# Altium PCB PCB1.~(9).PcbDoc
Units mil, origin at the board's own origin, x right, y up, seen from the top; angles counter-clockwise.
Board outline 1890 x 1900 mil, 2 copper layers (Top Layer, Bottom Layer); 27 components, 29 nets, 115 pads, 22 vias.
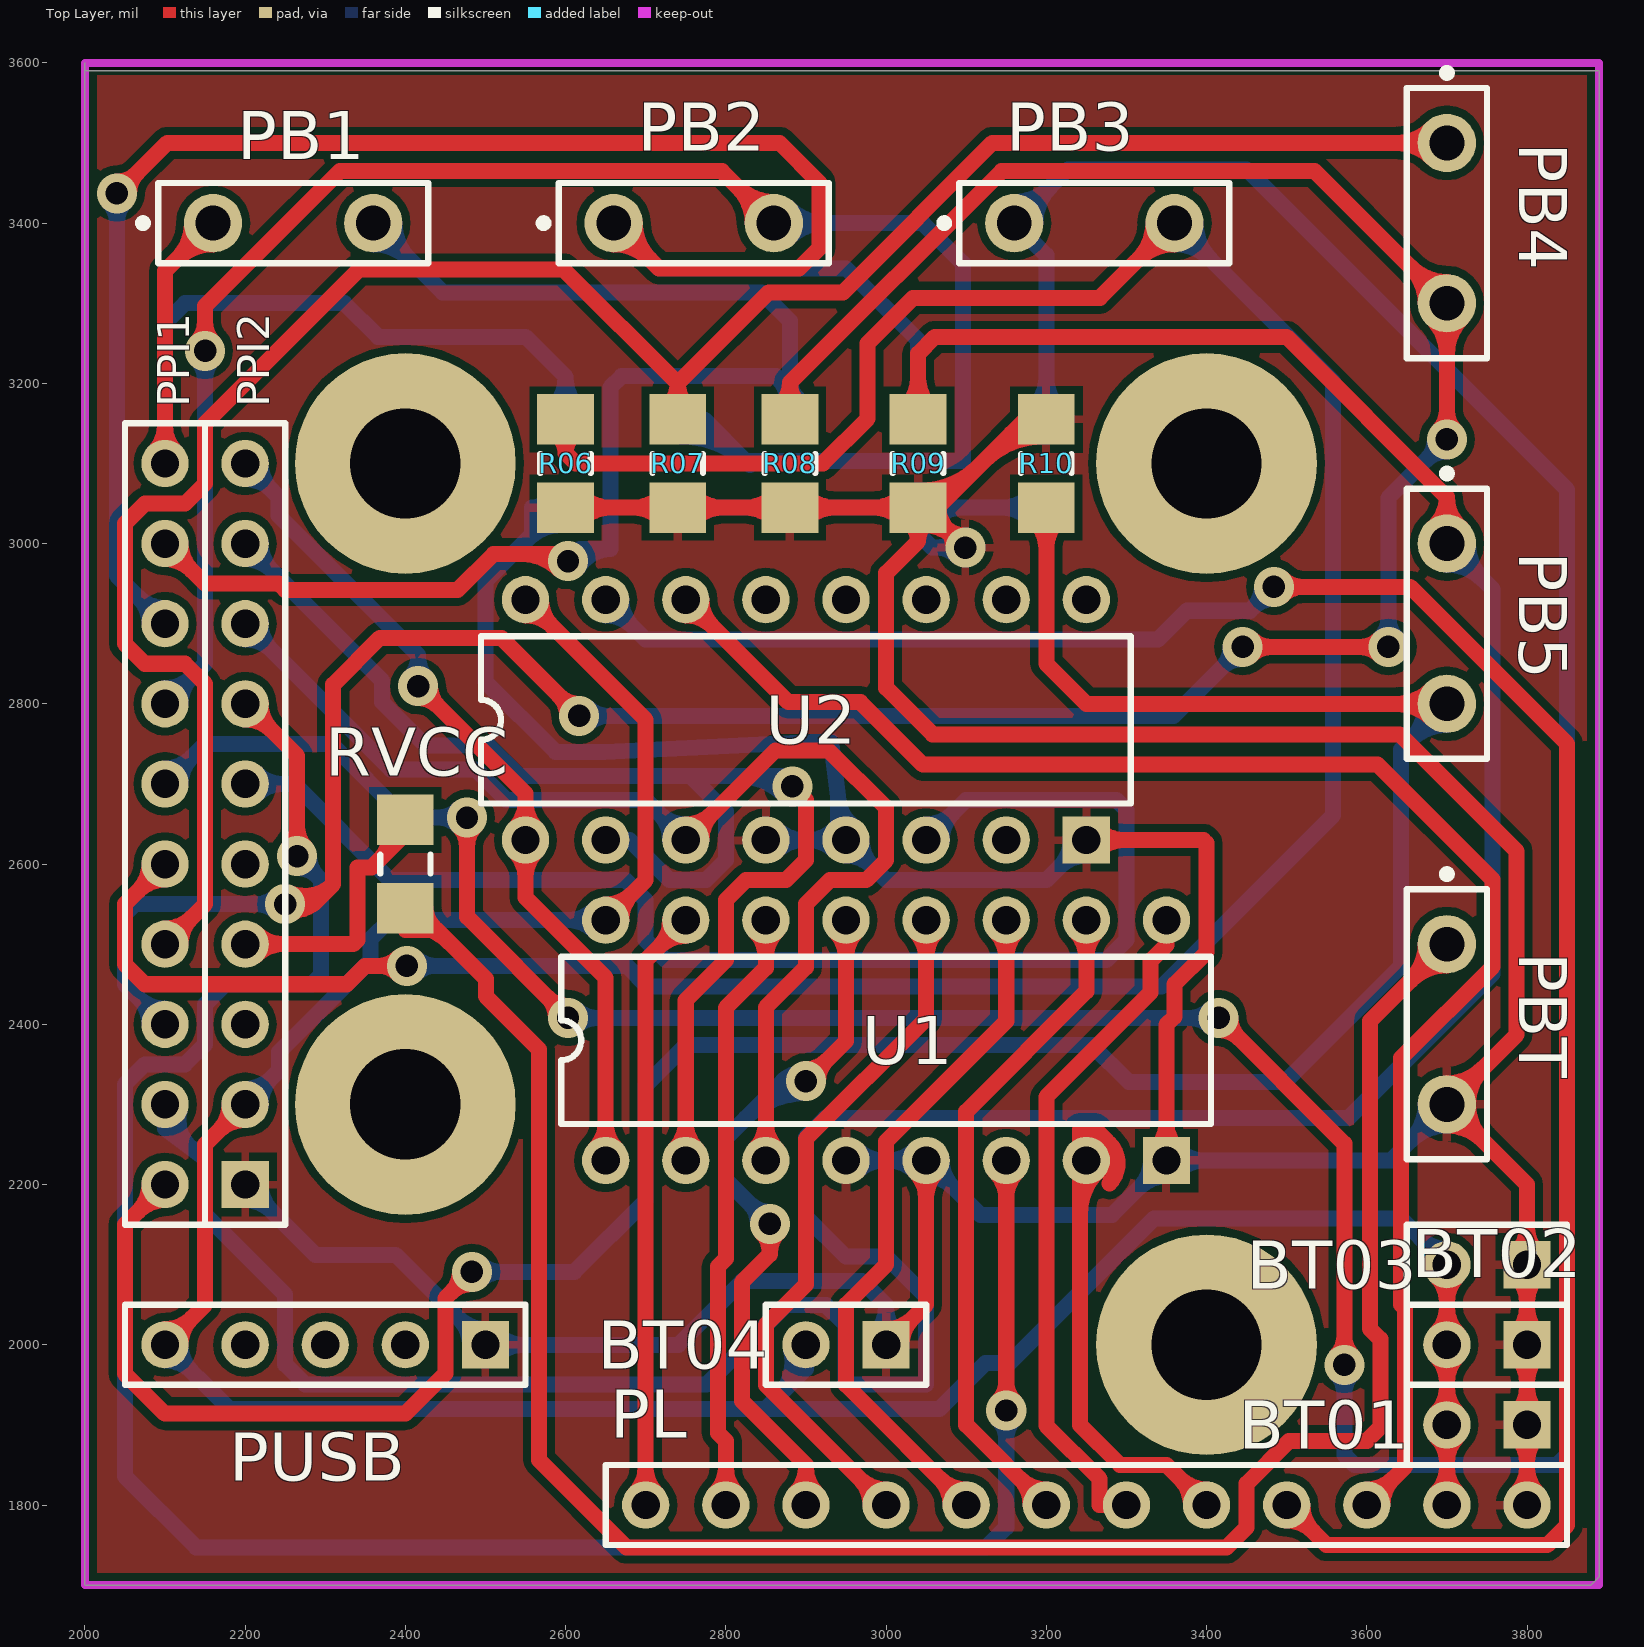
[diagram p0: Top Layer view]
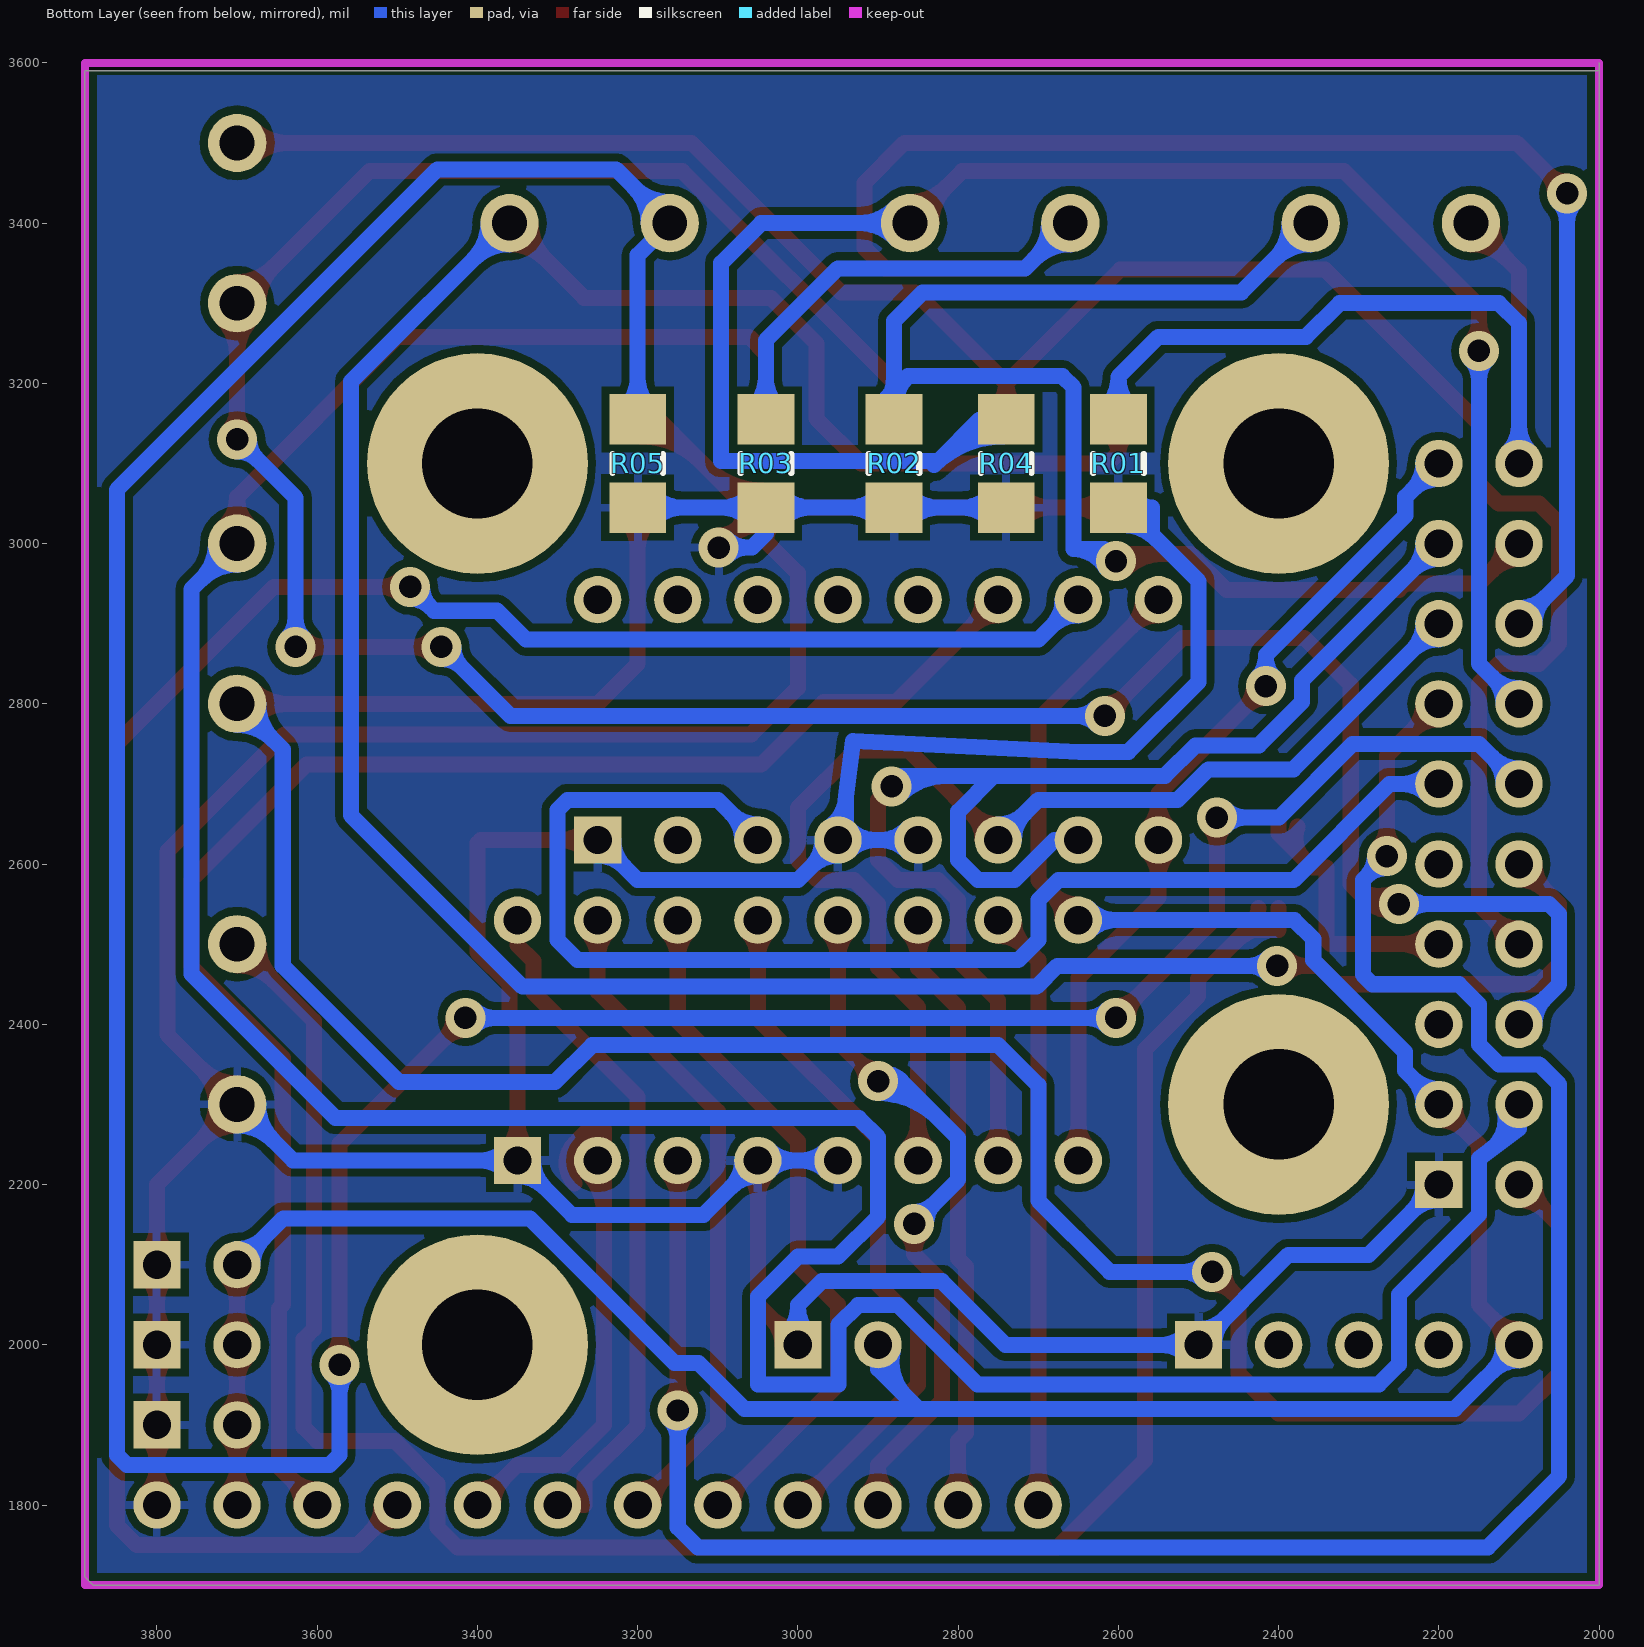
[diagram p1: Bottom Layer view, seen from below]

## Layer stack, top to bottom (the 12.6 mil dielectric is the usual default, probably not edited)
Top Layer: signal copper 1.4
Dielectric: dielectric 12.6, FR-4, Dk 4.8
Bottom Layer: signal copper 1.4

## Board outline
2010,3590 3890,3590 3890,1710 3880,1700 2000,1700 2000,3600 2000,3590

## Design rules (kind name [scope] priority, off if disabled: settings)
Clearance [All] p1: gap=10
ComponentClearance [All] p1: gap=10 collisioncheckmode=3 verticalgap=10
PolygonConnect [All] p1: connectstyle=Relief reliefconductorwidth=10 reliefentries=4 polygonreliefangle="90 Angle"
RoutingVias [All] p1: holewidth=28 width=50 viastyle="Through Hole" minholewidth=28 minwidth=50 maxholewidth=28 maxwidth=50
SolderMaskExpansion [All] p1: expansion=4
TestPointUsage [All] p1: valid=0 allowmultiple=FALSE
Testpoint [All] p1: side=15 testpointundercomponent=TRUE minsize=40 maxsize=100 preferedsize=60 minholesize=0 maxholesize=40 preferedholesize=32 testpointgrid=1 style=1023 order=0123456789
Width Width_2 [All] p1: maxlimit=30 minlimit=15 preferedwidth=20
Width Width_1 [InNet('VCC')] p2: maxlimit=30 minlimit=20 preferedwidth=30
Width [InNet('GND')] p3: maxlimit=30 minlimit=20 preferedwidth=30
18 further rules are at their usual default settings.

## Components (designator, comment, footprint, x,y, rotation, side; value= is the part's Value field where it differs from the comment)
BT01 "Header 2" HDR1X2 3800,1900 r180 top
BT02 "Header 2" HDR1X2 3800,2000 r180 top
BT03 "Header 2" HDR1X2 3800,2100 r180 top
BT04 "Header 2" HDR1X2 3000,2000 r180 top
PB1 "Header 2" SPST-2 2260,3400 r0 top
PB2 "Header 2" SPST-2 2760,3400 r0 top
PB3 "Header 2" SPST-2 3260,3400 r0 top
PB4 "Header 2" SPST-2 3700,3400 r270 top
PB5 "Header 2" SPST-2 3700,2900 r270 top
PBT "Header 2" SPST-2 3700,2400 r270 top
PL "Header 12" HDR1X12 2700,1800 r0 top
PPI1 "Header 10" HDR1X10#1 2100,3100 r270 top
PPI2 "Header 10" HDR1X10#2 2200,3100 r270 top
PUSB "Header 5" HDR1X5 2100,2000 r0 top
R01 "Res1" 3216[1206] 2600,3100 r90 bottom
R02 "Res1" 3216[1206] 2880,3100 r90 bottom
R03 "Res1" 3216[1206] 3040,3100 r90 bottom
R04 "Res1" 3216[1206] 2740,3100 r90 bottom
R05 "Res1" 3216[1206] 3200,3100 r90 bottom
R06 "Res1" 3216[1206] 2600,3100 r90 top
R07 "Res1" 3216[1206] 2740,3100 r90 top
R08 "Res1" 3216[1206] 2880,3100 r90 top
R09 "Res1" 3216[1206] 3040,3100 r90 top
R10 "Res1" 3216[1206] 3200,3100 r270 top
RVCC "Res1" 3216[1206] 2400,2600 r90 top
U1 "SN74HC138D" DIP-16 3000,2380 r0 top
U2 "SN74HC138D" DIP-16 2900,2780 r0 top

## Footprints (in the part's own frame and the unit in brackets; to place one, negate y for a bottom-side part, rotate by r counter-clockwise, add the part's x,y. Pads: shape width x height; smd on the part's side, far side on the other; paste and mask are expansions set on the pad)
3216[1206] [mm] "Chip Resistor; Body 3.2 x 1.6 mm (LxW typ)"
  rect 1.6x1.8 smd: 1(-1.4,0) 2(1.4,0)
  silkscreen extent -0.3,-0.8 0.3,0.8
DIP-16 [mm] "DIP; 16 Leads; Row Spacing 7.62 mm; Pitch 2.54 mm"
  round 1.5 hole 0.9: 1(-8.89,-3.81) 2(-6.35,-3.81) 3(-3.81,-3.81) 4(-1.27,-3.81) 5(1.27,-3.81) 6(3.81,-3.81) 7(6.35,-3.81) 9(8.89,3.81) 10(6.35,3.81) 11(3.81,3.81) 12(1.27,3.81) 13(-1.27,3.81) 14(-3.81,3.81) 15(-6.35,3.81) 16(-8.89,3.81)
  rect 1.5x1.5 hole 0.9: 8(8.89,-3.81)
  silkscreen extent -10.3,-2.65 10.3,2.65
HDR1X2 [mm] "Connector; Header; 2 Position"
  rect 1.5x1.5 hole 0.9: 1(0,0)
  round 1.5 hole 0.9: 2(2.54,0)
  silkscreen extent -1.27,-1.27 3.81,1.27
HDR1X5 [mm] "Connector; Header; 5 Position"
  round 1.5 hole 0.9: 1(0,0) 2(2.54,0) 3(5.08,0) 4(7.62,0)
  rect 1.5x1.5 hole 0.9: 5(10.16,0)
  silkscreen extent -1.27,-1.27 11.43,1.27
HDR1X10#1 [mm] "Connector; Header; 10 Position"
  round 1.5 hole 0.9: 1(0,0) 2(2.54,0) 3(5.08,0) 4(7.62,0) 5(10.16,0) 6(12.7,0) 7(15.24,0) 8(17.78,0) 9(20.32,0) 10(22.86,0)
  silkscreen extent -1.27,-1.27 24.13,1.27
HDR1X10#2 [mm] "Connector; Header; 10 Position"
  round 1.5 hole 0.9: 1(0,0) 2(2.54,0) 3(5.08,0) 4(7.62,0) 5(10.16,0) 6(12.7,0) 7(15.24,0) 8(17.78,0) 9(20.32,0)
  rect 1.5x1.5 hole 0.9: 10(22.86,0)
  silkscreen extent -1.27,-1.27 24.13,1.27
HDR1X12 [mm] "Connector; Header; 12 Position"
  round 1.5 hole 0.9: 1(0,0) 2(2.54,0) 3(5.08,0) 4(7.62,0) 5(10.16,0) 6(12.7,0) 7(15.24,0) 8(17.78,0) 9(20.32,0) 10(22.86,0) 11(25.4,0) 12(27.94,0)
  silkscreen extent -1.27,-1.27 29.21,1.27
SPST-2 [mm] "Circuit Breaker; 2 Leads"
  round 1.85 hole 1.1: 1(-2.54,0) 2(2.54,0)
  silkscreen extent -4.89,-1.27 4.28,1.27

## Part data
BT01 BT02 BT03 BT04 PB1 PB2 PB3 PB4 PB5 PBT: "Header, 2-Pin"
PL: "Header, 12-Pin"
PPI1 PPI2: "Header, 10-Pin"
PUSB: "Header, 5-Pin"
R01 R02 R03 R04 R05 R06 R07 R08 R09 R10 RVCC: "Resistor"
U1 U2: "3-Line to 8-Line Decoder / Demultiplexer"

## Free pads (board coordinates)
  round 275.59 hole 137.8: 0(3400,3100) 1(2400,3100) 3(3400,2000)
  round 275.59 hole 137.8 paste+0: 2(2400,2300)

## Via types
v1: diameter 50, hole 28, Top Layer to Bottom Layer, 22 vias

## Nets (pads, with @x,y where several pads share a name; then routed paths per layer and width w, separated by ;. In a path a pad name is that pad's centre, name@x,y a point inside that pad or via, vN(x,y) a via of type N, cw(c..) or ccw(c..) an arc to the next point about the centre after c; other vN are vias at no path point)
GND: BT01.1 BT02.1 BT03.1 BT04.1 PBT.2 PL.12 PPI2.10 PUSB.5 R01.1 R02.1 R03.1 R04.1 R05.1 R06.1 R07.1 R08.1 R09.1 R10.1 U1.4 U1.5 U1.8 U2.4 U2.5 U2.8 | length 14839.4
  Top Layer w20: R06.1 R07.1 R08.1 R09.1 ; BT04.1 3050,2050 U1.5 ; v1(3099,2995) R09.1@3049.12,3044.88 ; R10.1 3174.24,3155.12 3064,3044.88 R09.1@3049.12,3044.88 ; U2.8 3396,2630 3400,2626 3400,2490 3360,2450 3360,2409.43 3350,2399.43 U1.8 ; PL.12 BT01.1 BT02.1 BT03.1 3800,2200 PBT.2 3787,2387 3787,2616 3641,2762 3058,2762 3000,2820 3000,2963 3040,3003 ; 2655.83,3044.88 cw(c2655.83,3096.78) 2619.14,3060.08 ccw(c2655.83,3096.78) 2655.83,3044.88 ; 2655.83,3044.88 ccw(c2655.83,2992.99) 2619.14,3029.68 cw(c2655.83,2992.99) 2655.83,3044.88 ; 2684.17,3044.88 cw(c2684.17,2992.99) 2720.86,3029.68 ccw(c2684.17,2992.99) 2684.17,3044.88 ; 2684.17,3044.88 ccw(c2684.17,3096.78) 2720.86,3060.08 cw(c2684.17,3096.78) 2684.17,3044.88 ; 2795.83,3044.88 cw(c2795.83,3096.78) 2759.14,3060.08 ccw(c2795.83,3096.78) 2795.83,3044.88 ; 2795.83,3044.88 ccw(c2795.83,2992.99) 2759.14,3029.68 cw(c2795.83,2992.99) 2795.83,3044.88 ; 2824.17,3044.88 cw(c2824.17,2992.99) 2860.86,3029.68 ccw(c2824.17,2992.99) 2824.17,3044.88 ; 2824.17,3044.88 ccw(c2824.17,3096.78) 2860.86,3060.08 cw(c2824.17,3096.78) 2824.17,3044.88 ; 2935.83,3044.88 cw(c2935.83,3096.78) 2899.14,3060.08 ccw(c2935.83,3096.78) 2935.83,3044.88 ; 2935.83,3044.88 ccw(c2935.83,2992.99) 2899.14,3029.68 cw(c2935.83,2992.99) 2935.83,3044.88 ; 2984.17,3044.88 cw(c2984.17,2992.99) 3020.86,3029.68 ccw(c2984.17,2992.99) 2984.17,3044.88 ; 2984.17,3044.88 ccw(c2984.17,3096.78) 3020.86,3060.08 cw(c2984.17,3096.78) 2984.17,3044.88 ; 3033.34,2033.34 cw(c3000,2066.67) 3000,2019.53 ccw(c3000,2066.67) 3033.34,2033.34 ; 3033.34,2033.34 ccw(c3066.67,2000) 3019.53,2000 cw(c3066.67,2000) 3033.34,2033.34 ; 3040,3003 cw(c3070.05,3003) 3052.53,3027.42 ccw(c3070.05,3003) 3040,3003 ; 3040,3003 ccw(c3009.95,3003) 3027.47,3027.42 cw(c3009.95,3003) 3040,3003 ; 3040,3003 R09.1 ; R09.1 R09.1@3049.12,3044.88 ; 3050,2182.86 cw(c3097.14,2182.86) 3063.81,2216.19 ccw(c3097.14,2182.86) 3050,2182.86 ; 3050,2182.86 ccw(c3002.86,2182.86) 3036.19,2216.19 cw(c3002.86,2182.86) 3050,2182.86 ; R09.1@3073.39,3020.61 cw(c3047.79,2995) 3084,2995 ccw(c3047.79,2995) R09.1@3073.39,3020.61 ; R09.1@3073.39,3020.61 ccw(c3099,3046.21) 3099,3010 cw(c3099,3046.21) R09.1@3073.39,3020.61 ; 3297.14,2630 cw(c3297.14,2677.14) 3263.81,2643.81 ccw(c3297.14,2677.14) 3297.14,2630 ; 3297.14,2630 ccw(c3297.14,2582.86) 3263.81,2616.19 cw(c3297.14,2582.86) 3297.14,2630 ; 3350,2277.14 cw(c3302.86,2277.14) 3336.19,2243.81 ccw(c3302.86,2277.14) 3350,2277.14 ; 3350,2277.14 ccw(c3397.14,2277.14) 3363.81,2243.81 cw(c3397.14,2277.14) 3350,2277.14 ; PBT.2@3726.42,2300 cw(c3790.19,2300) 3745.1,2345.1 ; PBT.2@3726.42,2300 ccw(c3790.19,2300) 3745.1,2254.9 ; PBT.2@3726.42,2300 cw(c3790.19,2300) 3745.1,2345.1 ; PBT.2@3726.42,2300 ccw(c3790.19,2300) 3745.1,2254.9 ; 3745.1,2254.9 ccw(c3700,2209.81) 3700,2273.58 cw(c3700,2209.81) 3745.1,2254.9 ; 3745.1,2345.1 cw(c3700,2390.19) 3700,2326.42 ccw(c3700,2390.19) 3745.1,2345.1 ; 3800,1847.14 cw(c3752.86,1847.14) 3786.19,1813.81 ccw(c3752.86,1847.14) 3800,1847.14 ; 3800,1847.14 ccw(c3847.14,1847.14) 3813.81,1813.81 cw(c3847.14,1847.14) 3800,1847.14 ; 3800,1852.86 cw(c3847.14,1852.86) 3813.81,1886.19 ccw(c3847.14,1852.86) 3800,1852.86 ; 3800,1852.86 ccw(c3752.86,1852.86) 3786.19,1886.19 cw(c3752.86,1852.86) 3800,1852.86 ; 3800,1947.14 cw(c3752.86,1947.14) 3786.19,1913.81 ccw(c3752.86,1947.14) 3800,1947.14 ; 3800,1947.14 ccw(c3847.14,1947.14) 3813.81,1913.81 cw(c3847.14,1947.14) 3800,1947.14 ; 3800,1952.86 cw(c3847.14,1952.86) 3813.81,1986.19 ccw(c3847.14,1952.86) 3800,1952.86 ; 3800,1952.86 ccw(c3752.86,1952.86) 3786.19,1986.19 cw(c3752.86,1952.86) 3800,1952.86 ; 3800,2047.14 cw(c3752.86,2047.14) 3786.19,2013.81 ccw(c3752.86,2047.14) 3800,2047.14 ; 3800,2047.14 ccw(c3847.14,2047.14) 3813.81,2013.81 cw(c3847.14,2047.14) 3800,2047.14 ; 3800,2052.86 cw(c3847.14,2052.86) 3813.81,2086.19 ccw(c3847.14,2052.86) 3800,2052.86 ; 3800,2052.86 ccw(c3752.86,2052.86) 3786.19,2086.19 cw(c3752.86,2052.86) 3800,2052.86 ; 3800,2147.14 cw(c3752.86,2147.14) 3786.19,2113.81 ccw(c3752.86,2147.14) 3800,2147.14 ; 3800,2147.14 ccw(c3847.14,2147.14) 3813.81,2113.81 cw(c3847.14,2147.14) 3800,2147.14 ; R09.1@3043.94,3023.39 cw(c3043.94,2958.98) 3089.48,3004.52 ccw(c3043.94,2958.98) R09.1@3043.94,3023.39 ; R09.1@3043.94,3046.38 ccw(c3043.94,3098.43) 3080.74,3061.62 cw(c3043.94,3098.43) R09.1@3043.94,3046.38 ; R09.1@3043.94,3066.38 ccw(c3043.94,3166.71) 3114.88,3095.76 cw(c3043.94,3166.71) R09.1@3043.94,3066.38 ; R09.1@3065.43,3044.88 ccw(c3104.82,3044.88) 3076.97,3017.03 cw(c3104.82,3044.88) R09.1@3065.43,3044.88 ; 3122.11,3102.99 cw(c3196.06,3029.03) 3196.06,3133.62 ccw(c3196.06,3029.03) 3122.11,3102.99 ; 3156.25,3137.13 cw(c3196.06,3097.32) 3196.06,3153.62 ccw(c3196.06,3097.32) 3156.25,3137.13
  Bottom Layer w20: PPI2.10 2287.8,2112.2 2387.8,2112.2 PUSB.5 2740.94,2000 2820.47,2079.53 2970,2079.53 3000,2049.53 BT04.1 ; R01.1 2558,3044.88 ; R04.1 R02.1 R03.1 ; U2.4 U2.5@2940,2630 ; U1.4 U1.5 3118.02,2161.98 3281.98,2161.98 U1.8 3630,2230 PBT.2 ; v1(3099,2995) 3057.5,2995 3040,3012.5 R03.1 ; R05.1 R03.1 ; U2.8 3200,2580 3000,2580 U2.5 U2.5@2940,2630 ; 2233.34,2166.66 cw(c2266.67,2200) 2219.53,2200 ccw(c2266.67,2200) 2233.34,2166.66 ; 2233.34,2166.66 ccw(c2200,2133.33) 2200,2180.47 cw(c2200,2133.33) 2233.34,2166.66 ; 2466.66,2033.34 cw(c2433.33,2000) 2480.47,2000 ccw(c2433.33,2000) 2466.66,2033.34 ; 2466.66,2033.34 ccw(c2500,2066.67) 2500,2019.53 cw(c2500,2066.67) 2466.66,2033.34 ; 2547.14,2000 cw(c2547.14,2047.14) 2513.81,2013.81 ccw(c2547.14,2047.14) 2547.14,2000 ; 2547.14,2000 ccw(c2547.14,1952.86) 2513.81,1986.19 cw(c2547.14,1952.86) 2547.14,2000 ; 2558,3044.88 cw(c2558,3021.93) 2577.65,3033.78 ccw(c2558,3021.93) 2558,3044.88 ; 2558,3044.88 ccw(c2558,3067.83) 2577.65,3055.98 cw(c2558,3067.83) 2558,3044.88 ; 2558,3044.88 2558,3010.86 2500,2952.86 2500,2827.5 2587.5,2740 2648.45,2740 2931.45,2753.55 2940,2684.96 ; 2562.23,3015.09 ccw(c2532.43,3044.88) R01.1@2574.57,3044.88 ; 2562.23,3015.09 ccw(c2532.43,3044.88) R01.1@2574.57,3044.88 ; 2562.23,3015.09 ccw(c2532.43,3044.88) R01.1@2574.57,3044.88 ; 2562.23,3015.09 ccw(c2532.43,3044.88) R01.1@2574.57,3044.88 ; 2795.83,3044.88 cw(c2795.83,3096.78) 2759.14,3060.08 ccw(c2795.83,3096.78) 2795.83,3044.88 ; 2795.83,3044.88 ccw(c2795.83,2992.99) 2759.14,3029.68 cw(c2795.83,2992.99) 2795.83,3044.88 ; 2824.17,3044.88 cw(c2824.17,2992.99) 2860.86,3029.68 ccw(c2824.17,2992.99) 2824.17,3044.88 ; 2824.17,3044.88 ccw(c2824.17,3096.78) 2860.86,3060.08 cw(c2824.17,3096.78) 2824.17,3044.88 ; 2897.14,2630 cw(c2897.14,2677.14) 2863.81,2643.81 ccw(c2897.14,2677.14) 2897.14,2630 ; 2897.14,2630 ccw(c2897.14,2582.86) 2863.81,2616.19 cw(c2897.14,2582.86) 2897.14,2630 ; 2902.86,2630 cw(c2902.86,2582.86) 2936.19,2616.19 ccw(c2902.86,2582.86) 2902.86,2630 ; 2902.86,2630 ccw(c2902.86,2677.14) 2936.19,2643.81 cw(c2902.86,2677.14) 2902.86,2630 ; 2935.83,3044.88 cw(c2935.83,3096.78) 2899.14,3060.08 ccw(c2935.83,3096.78) 2935.83,3044.88 ; 2935.83,3044.88 ccw(c2935.83,2992.99) 2899.14,3029.68 cw(c2935.83,2992.99) 2935.83,3044.88 ; U2.5@2940,2630 2940,2684.96 ; 2940,2684.95 ccw(c2986.37,2684.95) 2960.78,2646.28 cw(c2986.37,2684.95) 2940,2684.95 ; 2983.34,2596.66 cw(c3016.67,2630) 2969.53,2630 ccw(c3016.67,2630) 2983.34,2596.66 ; 2983.34,2596.66 ccw(c2950,2563.33) 2950,2610.47 cw(c2950,2563.33) 2983.34,2596.66 ; 2984.17,3044.88 cw(c2984.17,2992.99) 3020.86,3029.68 ccw(c2984.17,2992.99) 2984.17,3044.88 ; 2984.17,3044.88 ccw(c2984.17,3096.78) 3020.86,3060.08 cw(c2984.17,3096.78) 2984.17,3044.88 ; 2997.14,2230 cw(c2997.14,2277.14) 2963.81,2243.81 ccw(c2997.14,2277.14) 2997.14,2230 ; 2997.14,2230 ccw(c2997.14,2182.86) 2963.81,2216.19 cw(c2997.14,2182.86) 2997.14,2230 ; 3000,2047.14 cw(c2952.86,2047.14) 2986.19,2013.81 ccw(c2952.86,2047.14) 3000,2047.14 ; 3000,2047.14 ccw(c3047.14,2047.14) 3013.81,2013.81 cw(c3047.14,2047.14) 3000,2047.14 ; 3002.86,2230 cw(c3002.86,2182.86) 3036.19,2216.19 ccw(c3002.86,2182.86) 3002.86,2230 ; 3002.86,2230 ccw(c3002.86,2277.14) 3036.19,2243.81 cw(c3002.86,2277.14) 3002.86,2230 ; 3062.79,2995 cw(c3062.79,2958.79) 3088.39,2984.39 ccw(c3062.79,2958.79) 3062.79,2995 ; 3062.79,2995 ccw(c3062.79,3031.21) 3088.39,3005.61 cw(c3062.79,3031.21) 3062.79,2995 ; 3083.34,2196.66 cw(c3116.67,2230) 3069.53,2230 ccw(c3116.67,2230) 3083.34,2196.66 ; 3083.34,2196.66 ccw(c3050,2163.33) 3050,2210.47 cw(c3050,2163.33) 3083.34,2196.66 ; 3095.83,3044.88 cw(c3095.83,3096.78) 3059.14,3060.08 ccw(c3095.83,3096.78) 3095.83,3044.88 ; 3095.83,3044.88 ccw(c3095.83,2992.99) 3059.14,3029.68 cw(c3095.83,2992.99) 3095.83,3044.88 ; 3144.17,3044.88 cw(c3144.17,2992.99) 3180.86,3029.68 ccw(c3144.17,2992.99) 3144.17,3044.88 ; 3144.17,3044.88 ccw(c3144.17,3096.78) 3180.86,3060.08 cw(c3144.17,3096.78) 3144.17,3044.88 ; 3216.66,2596.66 cw(c3250,2563.33) 3250,2610.47 ccw(c3250,2563.33) 3216.66,2596.66 ; 3216.66,2596.66 ccw(c3183.33,2630) 3230.47,2630 cw(c3183.33,2630) 3216.66,2596.66 ; 3316.66,2196.66 cw(c3350,2163.33) 3350,2210.47 ccw(c3350,2163.33) 3316.66,2196.66 ; 3316.66,2196.66 ccw(c3283.33,2230) 3330.47,2230 cw(c3283.33,2230) 3316.66,2196.66 ; 3397.14,2230 cw(c3397.14,2277.14) 3363.81,2243.81 ccw(c3397.14,2277.14) 3397.14,2230 ; 3397.14,2230 ccw(c3397.14,2182.86) 3363.81,2216.19 cw(c3397.14,2182.86) 3397.14,2230 ; 3654.9,2254.9 cw(c3700,2209.81) 3700,2273.58 ccw(c3700,2209.81) 3654.9,2254.9 ; 3654.9,2254.9 ccw(c3609.81,2300) 3673.58,2300 cw(c3609.81,2300) 3654.9,2254.9 ; 2552.47,3005.33 cw(c2596.06,2961.73) 2596.06,3023.39 ccw(c2596.06,2961.73) 2552.47,3005.33 ; 2555.98,3008.84 cw(c2591.45,2973.37) 2594.68,3023.43 ccw(c2591.45,2973.37) 2555.98,3008.84
NetPB1_1: PB1.1 PPI1.1 R01.2 | length 1760.8
  Top Layer w20: PPI1.1 2100,3340 PB1.1 ; 2100,3147.14 cw(c2052.86,3147.14) 2086.19,3113.81 ccw(c2052.86,3147.14) 2100,3147.14 ; 2100,3147.14 ccw(c2147.14,3147.14) 2113.81,3113.81 cw(c2147.14,3147.14) 2100,3147.14 ; 2114.9,3354.9 cw(c2160,3309.81) 2160,3373.58 ccw(c2160,3309.81) 2114.9,3354.9 ; 2114.9,3354.9 ccw(c2069.81,3400) 2133.58,3400 cw(c2069.81,3400) 2114.9,3354.9
  Bottom Layer w20: PPI1.1 2100,3275 2125,3300 2324,3300 2366,3258 2550,3258 2600,3208 R01.2 ; 2100,3147.14 cw(c2052.86,3147.14) 2086.19,3113.81 ccw(c2052.86,3147.14) 2100,3147.14 ; 2100,3147.14 ccw(c2147.14,3147.14) 2113.81,3113.81 cw(c2147.14,3147.14) 2100,3147.14 ; 2600,3207.01 cw(c2548.1,3207.01) 2584.8,3170.32 ccw(c2548.1,3207.01) 2600,3207.01 ; 2600,3207.01 ccw(c2651.9,3207.01) 2615.2,3170.32 cw(c2651.9,3207.01) 2600,3207.01
NetPB1_2: PB1.2 PPI1.2 R02.2 | length 2819
  Top Layer w20: PPI1.2 2150,2950 2242,2950 2249.8,2942.2 2465.36,2942.2 2510.16,2987 2594,2987 v1(2603,2978) ; 2133.34,2966.66 cw(c2166.67,3000) 2119.53,3000 ccw(c2166.67,3000) 2133.34,2966.66 ; 2133.34,2966.66 ccw(c2100,2933.33) 2100,2980.47 cw(c2100,2933.33) 2133.34,2966.66 ; 2545.06,2987 cw(c2545.06,2920.06) 2592.39,2967.39 ccw(c2545.06,2920.06) 2545.06,2987
  Bottom Layer w20: PB1.2 2446.42,3313.58 2844.42,3313.58 2880,3278 2880,3191.5 ; v1(2603,2978) 2618,2993 2656,2993 ; R02.2 2880,3191.5 ; 2405.1,3354.9 cw(c2450.19,3400) 2386.42,3400 ccw(c2450.19,3400) 2405.1,3354.9 ; 2405.1,3354.9 ccw(c2360,3309.81) 2360,3373.58 cw(c2360,3309.81) 2405.1,3354.9 ; 2656,2993 ccw(c2656,2946.19) 2615.86,2970.28 cw(c2656,2946.19) 2656,2993 ; 2656,2993 2656,3195 2670,3209 2862.5,3209 2880,3191.5 ; R02.2@2869.63,3173.95 ccw(c2859.96,3191.5) 2880,3191.5 ; R02.2@2869.63,3173.95 ccw(c2859.96,3191.5) 2880,3191.5 ; R02.2@2869.63,3173.95 ccw(c2859.96,3191.5) 2880,3191.5 ; R02.2@2869.63,3173.95 ccw(c2859.96,3191.5) 2880,3191.5 ; 2880,3191.5 ccw(c2900.04,3191.5) R02.2@2890.37,3173.95 ; 2880,3191.5 ccw(c2900.04,3191.5) R02.2@2890.37,3173.95 ; 2880,3191.5 ccw(c2900.04,3191.5) R02.2@2890.37,3173.95 ; 2880,3191.5 ccw(c2900.04,3191.5) R02.2@2890.37,3173.95 ; 2880,3207.01 cw(c2828.1,3207.01) 2864.8,3170.32 ccw(c2828.1,3207.01) 2880,3207.01 ; 2880,3207.01 ccw(c2931.9,3207.01) 2895.2,3170.32 cw(c2931.9,3207.01) 2880,3207.01 ; 2863.89,3207.61 cw(c2829.71,3173.43) 2874.67,3155.67 ccw(c2829.71,3173.43) 2863.89,3207.61 ; R02.2@2885.44,3186.06 cw(c2860.61,3161.22) 2893.27,3148.32 ccw(c2860.61,3161.22) R02.2@2885.44,3186.06
NetPB2_1: PB2.1 PPI1.3 R03.2 | length 3336.1
  Top Layer w20: v1(2040,3437) 2103,3500 2867,3500 2917,3450 2917,3369 2891.58,3343.58 2716.42,3343.58 PB2.1 ; 2065.61,3462.61 cw(c2040,3488.21) 2040,3452 ccw(c2040,3488.21) 2065.61,3462.61 ; 2065.61,3462.61 ccw(c2091.21,3437) 2055,3437 cw(c2091.21,3437) 2065.61,3462.61 ; 2705.1,3354.9 cw(c2750.19,3400) 2686.42,3400 ccw(c2750.19,3400) 2705.1,3354.9 ; 2705.1,3354.9 ccw(c2660,3309.81) 2660,3373.58 cw(c2660,3309.81) 2705.1,3354.9
  Bottom Layer w20: v1(2040,3437) 2040,2960 PPI1.3 ; PB2.1 2716.42,3343.58 2950,3343.58 3040,3253.58 R03.2 ; 2040,3400.79 cw(c2076.21,3400.79) 2050.61,3426.39 ccw(c2076.21,3400.79) 2040,3400.79 ; 2040,3400.79 ccw(c2003.79,3400.79) 2029.39,3426.39 cw(c2003.79,3400.79) 2040,3400.79 ; 2066.66,2933.34 cw(c2033.33,2900) 2080.47,2900 ccw(c2033.33,2900) 2066.66,2933.34 ; 2066.66,2933.34 ccw(c2100,2966.67) 2100,2919.53 cw(c2100,2966.67) 2066.66,2933.34 ; 2705.1,3354.9 cw(c2750.19,3400) 2686.42,3400 ccw(c2750.19,3400) 2705.1,3354.9 ; 2705.1,3354.9 ccw(c2660,3309.81) 2660,3373.58 cw(c2660,3309.81) 2705.1,3354.9 ; 3040,3207.01 cw(c2988.1,3207.01) 3024.8,3170.32 ccw(c2988.1,3207.01) 3040,3207.01 ; 3040,3207.01 ccw(c3091.9,3207.01) 3055.2,3170.32 cw(c3091.9,3207.01) 3040,3207.01
NetPB2_2: PB2.2 PPI1.4 R04.2 | length 3288.4
  Top Layer w20: v1(2150,3240.5) 2150,3296.68 2318.32,3465 2795,3465 PB2.2 ; 2150,3276.71 cw(c2113.79,3276.71) 2139.39,3251.11 ccw(c2113.79,3276.71) 2150,3276.71 ; 2150,3276.71 ccw(c2186.21,3276.71) 2160.61,3251.11 cw(c2186.21,3276.71) 2150,3276.71 ; 2814.9,3445.1 cw(c2769.81,3400) 2833.58,3400 ccw(c2769.81,3400) 2814.9,3445.1 ; 2814.9,3445.1 ccw(c2860,3490.19) 2860,3426.42 cw(c2860,3490.19) 2814.9,3445.1
  Bottom Layer w20: PPI1.4 2150,2850 v1(2150,3240.5) ; R04.2 2772.88,3155.12 2825,3103 3096,3103 3096,3350 3046,3400 PB2.2 ; 2133.34,2833.34 cw(c2100,2866.67) 2100,2819.53 ccw(c2100,2866.67) 2133.34,2833.34 ; 2133.34,2833.34 ccw(c2166.67,2800) 2119.53,2800 cw(c2166.67,2800) 2133.34,2833.34 ; 2150,3204.29 cw(c2186.21,3204.29) 2160.61,3229.89 ccw(c2186.21,3204.29) 2150,3204.29 ; 2150,3204.29 ccw(c2113.79,3204.29) 2139.39,3229.89 cw(c2113.79,3204.29) 2150,3204.29 ; 2923.78,3400 cw(c2923.78,3463.78) 2878.68,3418.68 ccw(c2923.78,3463.78) 2923.78,3400 ; 2923.78,3400 ccw(c2923.78,3336.22) 2878.68,3381.32 cw(c2923.78,3336.22) 2923.78,3400 ; R04.2@2743.94,3133.62 cw(c2743.94,3011.85) 2830.05,3097.95 ccw(c2743.94,3011.85) R04.2@2743.94,3133.62 ; R04.2@2743.94,3153.62 cw(c2743.94,3080.13) 2795.9,3132.1 ccw(c2743.94,3080.13) R04.2@2743.94,3153.62
NetPB3_1: PB3.1 PPI1.5 R05.2 | length 6219.9
  Top Layer w20: v1(2477,2658) 2477,2534 v1(2603,2408) ; v1(3415,2408) 3572,2251 v1(3572,1975) ; 2477,2621.79 cw(c2513.21,2621.79) 2487.61,2647.39 ccw(c2513.21,2621.79) 2477,2621.79 ; 2477,2621.79 ccw(c2440.79,2621.79) 2466.39,2647.39 cw(c2440.79,2621.79) 2477,2621.79 ; 2577.39,2433.61 cw(c2551.79,2408) 2588,2408 ccw(c2551.79,2408) 2577.39,2433.61 ; 2577.39,2433.61 ccw(c2603,2459.21) 2603,2423 cw(c2603,2459.21) 2577.39,2433.61 ; 3440.61,2382.39 cw(c3466.21,2408) 3430,2408 ccw(c3466.21,2408) 3440.61,2382.39 ; 3440.61,2382.39 ccw(c3415,2356.79) 3415,2393 cw(c3415,2356.79) 3440.61,2382.39 ; 3572,2011.21 cw(c3535.79,2011.21) 3561.39,1985.61 ccw(c3535.79,2011.21) 3572,2011.21 ; 3572,2011.21 ccw(c3608.21,2011.21) 3582.61,1985.61 cw(c3608.21,2011.21) 3572,2011.21
  Bottom Layer w20: PPI1.5 2150,2750 2307.57,2750 2399.57,2658 v1(2477,2658) ; v1(2603,2408) v1(3415,2408) ; R05.2 3200,3360 PB3.1 3227,3467 3450,3467 3850,3067 3850,1862.5 3837.5,1850 3584.5,1850 3572,1862.5 v1(3572,1975) ; 2133.34,2733.34 cw(c2100,2766.67) 2100,2719.53 ccw(c2100,2766.67) 2133.34,2733.34 ; 2133.34,2733.34 ccw(c2166.67,2700) 2119.53,2700 cw(c2166.67,2700) 2133.34,2733.34 ; 2440.79,2658 cw(c2440.79,2621.79) 2466.39,2647.39 ccw(c2440.79,2621.79) 2440.79,2658 ; 2440.79,2658 ccw(c2440.79,2694.21) 2466.39,2668.61 cw(c2440.79,2694.21) 2440.79,2658 ; 2639.21,2408 cw(c2639.21,2444.21) 2613.61,2418.61 ccw(c2639.21,2444.21) 2639.21,2408 ; 2639.21,2408 ccw(c2639.21,2371.79) 2613.61,2397.39 cw(c2639.21,2371.79) 2639.21,2408 ; 3200,3207.01 cw(c3148.1,3207.01) 3184.8,3170.32 ccw(c3148.1,3207.01) 3200,3207.01 ; 3200,3207.01 ccw(c3251.9,3207.01) 3215.2,3170.32 cw(c3251.9,3207.01) 3200,3207.01 ; 3205.1,3445.1 cw(c3160,3490.19) 3160,3426.42 ccw(c3160,3490.19) 3205.1,3445.1 ; 3205.1,3445.1 ccw(c3250.19,3400) 3186.42,3400 cw(c3250.19,3400) 3205.1,3445.1 ; 3378.79,2408 cw(c3378.79,2371.79) 3404.39,2397.39 ccw(c3378.79,2371.79) 3378.79,2408 ; 3378.79,2408 ccw(c3378.79,2444.21) 3404.39,2418.61 cw(c3378.79,2444.21) 3378.79,2408 ; 3572,1938.79 cw(c3608.21,1938.79) 3582.61,1964.39 ccw(c3608.21,1938.79) 3572,1938.79 ; 3572,1938.79 ccw(c3535.79,1938.79) 3561.39,1964.39 cw(c3535.79,1938.79) 3572,1938.79
NetPB3_2: PB3.2 PPI1.6 R06.2 | length 4475.3
  Top Layer w20: PPI1.6 2050,2550 2050,2475 2075,2450 2326.84,2450 2349.84,2473 v1(2402,2473) ; R06.2 2600,3112.5 ; PB3.2 3266.75,3306.75 3033.68,3306.75 2976.93,3250 2976.93,3155.93 2921,3100 2612.5,3100 2600,3112.5 ; 2066.66,2566.66 cw(c2100,2533.33) 2100,2580.47 ccw(c2100,2533.33) 2066.66,2566.66 ; 2066.66,2566.66 ccw(c2033.33,2600) 2080.47,2600 cw(c2033.33,2600) 2066.66,2566.66 ; 2365.79,2473 cw(c2365.79,2436.79) 2391.39,2462.39 ccw(c2365.79,2436.79) 2365.79,2473 ; 2365.79,2473 ccw(c2365.79,2509.21) 2391.39,2483.61 cw(c2365.79,2509.21) 2365.79,2473 ; 2600,3112.5 cw(c2631.49,3112.5) 2612.78,3137.83 ccw(c2631.49,3112.5) 2600,3112.5 ; 2600,3112.5 ccw(c2568.51,3112.5) 2587.22,3137.83 cw(c2568.51,3112.5) 2600,3112.5 ; 3314.9,3354.9 cw(c3360,3309.81) 3360,3373.58 ccw(c3360,3309.81) 3314.9,3354.9 ; 3314.9,3354.9 ccw(c3269.81,3400) 3333.58,3400 cw(c3269.81,3400) 3314.9,3354.9
  Bottom Layer w20: v1(2402,2473) 2676.19,2473 2702.19,2447 3344,2447 3558,2661 3558,3202 PB3.2 ; 2438.21,2473 cw(c2438.21,2509.21) 2412.61,2483.61 ccw(c2438.21,2509.21) 2438.21,2473 ; 2438.21,2473 ccw(c2438.21,2436.79) 2412.61,2462.39 cw(c2438.21,2436.79) 2438.21,2473 ; 3405.1,3354.9 cw(c3450.19,3400) 3386.42,3400 ccw(c3450.19,3400) 3405.1,3354.9 ; 3405.1,3354.9 ccw(c3360,3309.81) 3360,3373.58 cw(c3360,3309.81) 3405.1,3354.9
NetPB4_1: PB4.1 PPI1.7 R07.2 | length 3147.1
  Top Layer w20: PPI1.7 2150,2550 2150,2825 2125,2850 2075,2850 2050,2875 2050,3025 2075,3050 2125,3050 2150,3075 2150,3150 2342,3342 2598,3342 2740,3200 ; R07.2 2740,3200 ; PB4.1 3132.84,3500 2946.42,3313.58 2853.58,3313.58 2740,3200 ; 2133.34,2533.34 cw(c2100,2566.67) 2100,2519.53 ccw(c2100,2566.67) 2133.34,2533.34 ; 2133.34,2533.34 ccw(c2166.67,2500) 2119.53,2500 cw(c2166.67,2500) 2133.34,2533.34 ; 2740,3200 cw(c2703.9,3200) 2726.53,3171.87 ccw(c2703.9,3200) 2740,3200 ; 2740,3200 ccw(c2776.1,3200) 2753.47,3171.87 cw(c2776.1,3200) 2740,3200 ; 3636.22,3500 cw(c3636.22,3436.22) 3681.32,3481.32 ccw(c3636.22,3436.22) 3636.22,3500 ; 3636.22,3500 ccw(c3636.22,3563.78) 3681.32,3518.68 cw(c3636.22,3563.78) 3636.22,3500
NetPB4_2: PB4.2 PPI1.8 R08.2 | length 5621.2
  Top Layer w20: v1(2250,2550) 2285,2550 ; v1(2617,2785) 2519.8,2882.2 2368.2,2882.2 2310,2824 2310,2575 ; R08.2 2880,3200.79 ; v1(3445,2871) v1(3627,2871) ; v1(3700,3130) PB4.2 3535,3465 3144.21,3465 2880,3200.79 ; 2285,2550 cw(c2285,2583.33) 2260.86,2560.34 ccw(c2285,2583.33) 2285,2550 ; 2285,2550 ccw(c2285,2516.67) 2260.86,2539.66 cw(c2285,2516.67) 2285,2550 ; 2285,2550 2310,2575 ; 2310,2575 cw(c2274.42,2610.57) 2255.61,2563.91 ccw(c2274.42,2610.57) 2310,2575 ; 2591.39,2810.61 cw(c2565.79,2785) 2602,2785 ccw(c2565.79,2785) 2591.39,2810.61 ; 2591.39,2810.61 ccw(c2617,2836.21) 2617,2800 cw(c2617,2836.21) 2591.39,2810.61 ; 2880,3200.79 cw(c2842.22,3200.79) 2866.3,3171.68 ccw(c2842.22,3200.79) 2880,3200.79 ; 2880,3200.79 ccw(c2917.78,3200.79) 2893.7,3171.68 cw(c2917.78,3200.79) 2880,3200.79 ; 3481.21,2871 cw(c3481.21,2907.21) 3455.61,2881.61 ccw(c3481.21,2907.21) 3481.21,2871 ; 3481.21,2871 ccw(c3481.21,2834.79) 3455.61,2860.39 cw(c3481.21,2834.79) 3481.21,2871 ; 3590.79,2871 cw(c3590.79,2834.79) 3616.39,2860.39 ccw(c3590.79,2834.79) 3590.79,2871 ; 3590.79,2871 ccw(c3590.79,2907.21) 3616.39,2881.61 cw(c3590.79,2907.21) 3590.79,2871 ; 3654.9,3345.1 cw(c3609.81,3300) 3673.58,3300 ccw(c3609.81,3300) 3654.9,3345.1 ; 3654.9,3345.1 ccw(c3700,3390.19) 3700,3326.42 cw(c3700,3390.19) 3654.9,3345.1 ; 3700,3166.21 cw(c3663.79,3166.21) 3689.39,3140.61 ccw(c3663.79,3166.21) 3700,3166.21 ; 3700,3166.21 ccw(c3736.21,3166.21) 3710.61,3140.61 cw(c3736.21,3166.21) 3700,3166.21 ; 3700,3236.22 cw(c3763.78,3236.22) 3718.68,3281.32 ccw(c3763.78,3236.22) 3700,3236.22 ; 3700,3236.22 ccw(c3636.22,3236.22) 3681.32,3281.32 cw(c3636.22,3236.22) 3700,3236.22 ; v1@2248.13,2545.36 ccw(c2262.13,2580.1) 2288.61,2553.61 cw(c2262.13,2580.1) v1@2248.13,2545.36
  Bottom Layer w20: PPI1.8 2050,2450 2050,2537.5 2062.5,2550 v1(2250,2550) ; v1(2617,2785) 3359,2785 v1(3445,2871) ; v1(3627,2871) 3627,3057 v1(3700,3130) ; 2066.66,2433.34 cw(c2033.33,2400) 2080.47,2400 ccw(c2033.33,2400) 2066.66,2433.34 ; 2066.66,2433.34 ccw(c2100,2466.67) 2100,2419.53 cw(c2100,2466.67) 2066.66,2433.34 ; 2213.79,2550 cw(c2213.79,2513.79) 2239.39,2539.39 ccw(c2213.79,2513.79) 2213.79,2550 ; 2213.79,2550 ccw(c2213.79,2586.21) 2239.39,2560.61 cw(c2213.79,2586.21) 2213.79,2550 ; 2653.21,2785 cw(c2653.21,2821.21) 2627.61,2795.61 ccw(c2653.21,2821.21) 2653.21,2785 ; 2653.21,2785 ccw(c2653.21,2748.79) 2627.61,2774.39 cw(c2653.21,2748.79) 2653.21,2785 ; 3419.39,2845.39 cw(c3445,2819.79) 3445,2856 ccw(c3445,2819.79) 3419.39,2845.39 ; 3419.39,2845.39 ccw(c3393.79,2871) 3430,2871 cw(c3393.79,2871) 3419.39,2845.39 ; 3627,2907.21 cw(c3590.79,2907.21) 3616.39,2881.61 ccw(c3590.79,2907.21) 3627,2907.21 ; 3627,2907.21 ccw(c3663.21,2907.21) 3637.61,2881.61 cw(c3663.21,2907.21) 3627,2907.21 ; 3674.39,3104.39 cw(c3700,3078.79) 3700,3115 ccw(c3700,3078.79) 3674.39,3104.39 ; 3674.39,3104.39 ccw(c3648.79,3130) 3685,3130 cw(c3648.79,3130) 3674.39,3104.39
NetPB5_1: PB5.1 PPI1.9 R09.2 | length 4860.3
  Top Layer w20: R09.2 3040,3237 3061,3258 3500,3258 3700,3058 ; PB5.1 3700,3058 ; 3040,3207.01 cw(c2988.1,3207.01) 3024.8,3170.32 ccw(c2988.1,3207.01) 3040,3207.01 ; 3040,3207.01 ccw(c3091.9,3207.01) 3055.2,3170.32 cw(c3091.9,3207.01) 3040,3207.01 ; 3700,3058 cw(c3649.54,3058) 3682.66,3019.93 ccw(c3649.54,3058) 3700,3058 ; 3700,3058 ccw(c3750.46,3058) 3717.34,3019.93 cw(c3750.46,3058) 3700,3058
  Bottom Layer w20: PPI1.9 2100,2269.76 2150,2232.57 2150,2162.5 2250,2062.5 2250,1975.47 2275,1950.47 2775.94,1950.47 2875,2049.53 2925,2049.53 2949.53,2025 2949.53,1950.47 3050,1950.47 3050,2060 3000,2110 2950,2110 2900,2160 2900,2259 2924,2283 3577,2283 3757,2463 3757,2943 PB5.1 ; 3745.1,2954.9 cw(c3790.19,3000) 3726.42,3000 ccw(c3790.19,3000) 3745.1,2954.9 ; 3745.1,2954.9 ccw(c3700,2909.81) 3700,2973.58 cw(c3700,2909.81) 3745.1,2954.9 ; PPI1.9@2099.55,2300.14 ccw(c2134.44,2289.58) 2112.68,2260.33 cw(c2134.44,2289.58) PPI1.9@2099.55,2300.14 ; PPI1.9@2118.69,2294.34 ccw(c2163.39,2280.82) 2135.52,2243.34 cw(c2163.39,2280.82) PPI1.9@2118.69,2294.34
NetPB5_2: PB5.2 PPI1.10 R10.2 | length 4285.1
  Top Layer w20: PPI1.10 2050,2150 2050,1964 2100,1914 2400,1914 2450,1964 2450,2058 v1(2483,2091) ; R10.2 3200,2850 3250,2800 PB5.2 ; 2066.66,2166.66 cw(c2100,2133.33) 2100,2180.47 ccw(c2100,2133.33) 2066.66,2166.66 ; 2066.66,2166.66 ccw(c2033.33,2200) 2080.47,2200 cw(c2033.33,2200) 2066.66,2166.66 ; 2457.39,2065.39 cw(c2483,2039.79) 2483,2076 ccw(c2483,2039.79) 2457.39,2065.39 ; 2457.39,2065.39 ccw(c2431.79,2091) 2468,2091 cw(c2431.79,2091) 2457.39,2065.39 ; 3200,2992.99 cw(c3251.9,2992.99) 3215.2,3029.68 ccw(c3251.9,2992.99) 3200,2992.99 ; 3200,2992.99 ccw(c3148.1,2992.99) 3184.8,3029.68 cw(c3148.1,2992.99) 3200,2992.99 ; 3636.22,2800 cw(c3636.22,2736.22) 3681.32,2781.32 ccw(c3636.22,2736.22) 3636.22,2800 ; 3636.22,2800 ccw(c3636.22,2863.78) 3681.32,2818.68 cw(c3636.22,2863.78) 3636.22,2800
  Bottom Layer w20: v1(2483,2091) 2611,2091 2700,2180 2700,2324 2750,2374 3257,2374 3303,2328 3498,2328 3643,2473 3643,2743 PB5.2 ; 2519.21,2091 cw(c2519.21,2127.21) 2493.61,2101.61 ccw(c2519.21,2127.21) 2519.21,2091 ; 2519.21,2091 ccw(c2519.21,2054.79) 2493.61,2080.39 cw(c2519.21,2054.79) 2519.21,2091 ; 3654.9,2754.9 cw(c3700,2709.81) 3700,2773.58 ccw(c3700,2709.81) 3654.9,2754.9 ; 3654.9,2754.9 ccw(c3609.81,2800) 3673.58,2800 cw(c3609.81,2800) 3654.9,2754.9
NetPBT_1: PBT.1 RVCC.1 | length 3107.2
  Top Layer w20: RVCC.1 2400,2518 2439,2518 2500.38,2456.62 2500.38,2435.07 2567,2368.45 2567,1856 2676,1747 3425,1747 3450,1772 3450,1826.84 3503.16,1880 3600,1880 3617,1897 3617,2007 3604,2020 3604,2404 PBT.1 ; RVCC.1@2425.43,2544.88 ccw(c2457.58,2544.88) RVCC.1@2434.85,2522.15 ; RVCC.1@2425.43,2544.88 ccw(c2457.58,2544.88) RVCC.1@2434.85,2522.15 ; RVCC.1@2425.43,2544.88 ccw(c2457.58,2544.88) RVCC.1@2434.85,2522.15 ; RVCC.1@2425.43,2544.88 ccw(c2457.58,2544.88) RVCC.1@2434.85,2522.15 ; 3654.9,2454.9 cw(c3700,2409.81) 3700,2473.58 ccw(c3700,2409.81) 3654.9,2454.9 ; 3654.9,2454.9 ccw(c3609.81,2500) 3673.58,2500 cw(c3609.81,2500) 3654.9,2454.9 ; RVCC.1@2403.94,2523.39 cw(c2403.94,2451.74) 2454.6,2502.4 ccw(c2403.94,2451.74) RVCC.1@2403.94,2523.39 ; RVCC.1@2408.64,2523.91 cw(c2416.78,2487.6) 2443.09,2513.91 ccw(c2416.78,2487.6) RVCC.1@2408.64,2523.91
NetPL_1: PL.1 U1.15 | length 1046.9
  Top Layer w20: PL.1 2700,2480 U1.15 ; 2700,1847.14 cw(c2652.86,1847.14) 2686.19,1813.81 ccw(c2652.86,1847.14) 2700,1847.14 ; 2700,1847.14 ccw(c2747.14,1847.14) 2713.81,1813.81 cw(c2747.14,1847.14) 2700,1847.14 ; 2716.66,2496.66 cw(c2750,2463.33) 2750,2510.47 ccw(c2750,2463.33) 2716.66,2496.66 ; 2716.66,2496.66 ccw(c2683.33,2530) 2730.47,2530 cw(c2683.33,2530) 2716.66,2496.66
NetPL_2: PL.2 U1.14 | length 1055.2
  Top Layer w20: PL.2 2800,1880 2790,1890 2790,2097.67 2800,2107.67 2800,2420.47 2850,2470.47 U1.14 ; 2800,1847.14 cw(c2752.86,1847.14) 2786.19,1813.81 ccw(c2752.86,1847.14) 2800,1847.14 ; 2800,1847.14 ccw(c2847.14,1847.14) 2813.81,1813.81 cw(c2847.14,1847.14) 2800,1847.14 ; 2850,2482.86 cw(c2897.14,2482.86) 2863.81,2516.19 ccw(c2897.14,2482.86) 2850,2482.86 ; 2850,2482.86 ccw(c2802.86,2482.86) 2836.19,2516.19 cw(c2802.86,2482.86) 2850,2482.86
NetPL_3: PL.3 U1.13 | length 1994.7
  Top Layer w20: v1(2855,2151) 2855,2113 2820,2078 2820,1930 2900,1850 PL.3 ; v1(2900,2329) 2950,2379 U1.13 ; 2855,2114.79 cw(c2891.21,2114.79) 2865.61,2140.39 ccw(c2891.21,2114.79) 2855,2114.79 ; 2855,2114.79 ccw(c2818.79,2114.79) 2844.39,2140.39 cw(c2818.79,2114.79) 2855,2114.79 ; 2900,1847.14 cw(c2852.86,1847.14) 2886.19,1813.81 ccw(c2852.86,1847.14) 2900,1847.14 ; 2900,1847.14 ccw(c2947.14,1847.14) 2913.81,1813.81 cw(c2947.14,1847.14) 2900,1847.14 ; 2925.61,2354.61 cw(c2900,2380.21) 2900,2344 ccw(c2900,2380.21) 2925.61,2354.61 ; 2925.61,2354.61 ccw(c2951.21,2329) 2915,2329 cw(c2951.21,2329) 2925.61,2354.61 ; 2950,2482.86 cw(c2997.14,2482.86) 2963.81,2516.19 ccw(c2997.14,2482.86) 2950,2482.86 ; 2950,2482.86 ccw(c2902.86,2482.86) 2936.19,2516.19 cw(c2902.86,2482.86) 2950,2482.86
  Bottom Layer w20: v1(2855,2151) 2800,2206 2800,2258 2871,2329 ; v1(2900,2329) 2871,2329 ; 2829.39,2176.61 cw(c2803.79,2151) 2840,2151 ccw(c2803.79,2151) 2829.39,2176.61 ; 2829.39,2176.61 ccw(c2855,2202.21) 2855,2166 cw(c2855,2202.21) 2829.39,2176.61 ; 2871,2329 cw(c2871,2308.47) 2887.76,2320.33 ccw(c2871,2308.47) 2871,2329 ; 2871,2329 ccw(c2871,2349.53) 2887.76,2337.67 cw(c2871,2349.53) 2871,2329 ; 2824.89,2282.89 cw(c2900,2207.77) 2900,2314 ccw(c2900,2207.77) 2824.89,2282.89 ; 2856.5,2314.5 cw(c2875.2,2295.81) 2891.02,2316.98 ccw(c2875.2,2295.81) 2856.5,2314.5 ; 2859.03,2317.03 cw(c2900,2276.06) 2900,2334 ccw(c2900,2276.06) 2859.03,2317.03 ; 2872.84,2330.84 cw(c2889.17,2314.5) 2902.99,2333.01 ccw(c2889.17,2314.5) 2872.84,2330.84
NetPL_4: PL.4 U1.12 | length 1171.2
  Top Layer w20: PL.4 2850,1950 2850,2025 2900,2075 2900,2257 3050,2407 U1.12 ; 2966.66,1833.34 cw(c2933.33,1800) 2980.47,1800 ccw(c2933.33,1800) 2966.66,1833.34 ; 2966.66,1833.34 ccw(c3000,1866.67) 3000,1819.53 cw(c3000,1866.67) 2966.66,1833.34 ; 3050,2482.86 cw(c3097.14,2482.86) 3063.81,2516.19 ccw(c3097.14,2482.86) 3050,2482.86 ; 3050,2482.86 ccw(c3002.86,2482.86) 3036.19,2516.19 cw(c3002.86,2482.86) 3050,2482.86
NetPL_5: PL.5 U1.11 | length 1171.2
  Top Layer w20: PL.5 2950,1950 2950,2050 3000,2100 3000,2254 3150,2404 U1.11 ; 3066.66,1833.34 cw(c3033.33,1800) 3080.47,1800 ccw(c3033.33,1800) 3066.66,1833.34 ; 3066.66,1833.34 ccw(c3100,1866.67) 3100,1819.53 cw(c3100,1866.67) 3066.66,1833.34 ; 3150,2482.86 cw(c3197.14,2482.86) 3163.81,2516.19 ccw(c3197.14,2482.86) 3150,2482.86 ; 3150,2482.86 ccw(c3102.86,2482.86) 3136.19,2516.19 cw(c3102.86,2482.86) 3150,2482.86
NetPL_6: PL.6 U1.10 | length 1129.8
  Top Layer w20: PL.6 3100,1900 3100,2291 3250,2441 U1.10 ; 3166.66,1833.34 cw(c3133.33,1800) 3180.47,1800 ccw(c3133.33,1800) 3166.66,1833.34 ; 3166.66,1833.34 ccw(c3200,1866.67) 3200,1819.53 cw(c3200,1866.67) 3166.66,1833.34 ; 3250,2482.86 cw(c3297.14,2482.86) 3263.81,2516.19 ccw(c3297.14,2482.86) 3250,2482.86 ; 3250,2482.86 ccw(c3202.86,2482.86) 3236.19,2516.19 cw(c3202.86,2482.86) 3250,2482.86
NetPL_7: PL.7 U1.9 | length 853.2
  Top Layer w20: PL.7 3266.5,1800 3266.5,1832.5 3200,1899 3200,2309.43 3330,2439.43 3330,2478.87 3350,2498.87 U1.9
NetPL_8: PL.8 U1.7 | length 1183
  Top Layer w20: U1.7 3275,2255 3261,2269 3250,2269 3242,2269 ; PL.8 3350,1850 3292,1850 3242,1900 3242,2230 3242,2269 ; 3242,2269 ccw(c3263.86,2269) 3256.54,2248.4 cw(c3263.86,2269) 3242,2269 ; 3366.66,1833.34 cw(c3333.33,1800) 3380.47,1800 ccw(c3333.33,1800) 3366.66,1833.34 ; 3366.66,1833.34 ccw(c3400,1866.67) 3400,1819.53 cw(c3400,1866.67) 3366.66,1833.34 ; 3242,2163.54 cw(c3316.46,2163.54) 3263.81,2216.19 ccw(c3316.46,2163.54) 3242,2163.54 ; 3264.42,2265.58 cw(c3239.37,2240.52) 3264.55,2215.59 ccw(c3239.37,2240.52) 3264.42,2265.58 ; 3278.64,2251.36 cw(c3253.65,2226.38) 3278.76,2201.52 ccw(c3253.65,2226.38) 3278.64,2251.36
NetPL_9: PL.9 U2.15 | length 3209
  Top Layer w20: v1(3484,2946) 3654,2946 3850,2750 3850,1775 3825,1750 3550,1750 PL.9 ; 3520.21,2946 cw(c3520.21,2982.21) 3494.61,2956.61 ccw(c3520.21,2982.21) 3520.21,2946 ; 3520.21,2946 ccw(c3520.21,2909.79) 3494.61,2935.39 cw(c3520.21,2909.79) 3520.21,2946 ; 3533.34,1766.66 cw(c3566.67,1800) 3519.53,1800 ccw(c3566.67,1800) 3533.34,1766.66 ; 3533.34,1766.66 ccw(c3500,1733.33) 3500,1780.47 cw(c3500,1733.33) 3533.34,1766.66
  Bottom Layer w20: U2.15 2700,2880 3339.28,2880 3375.44,2916.17 3454.17,2916.17 v1(3484,2946) ; 2683.34,2896.66 cw(c2716.67,2930) 2669.53,2930 ccw(c2716.67,2930) 2683.34,2896.66 ; 2683.34,2896.66 ccw(c2650,2863.33) 2650,2910.47 cw(c2650,2863.33) 2683.34,2896.66 ; 3458.39,2920.39 cw(c3484,2894.79) 3484,2931 ccw(c3484,2894.79) 3458.39,2920.39 ; 3458.39,2920.39 ccw(c3432.79,2946) 3469,2946 cw(c3432.79,2946) 3458.39,2920.39
NetPL_10: PL.10 U2.14 | length 2297.5
  Top Layer w20: U2.14 2878,2802 2967.98,2802 3045.98,2724 3613.58,2724 3757,2580.58 3757,2472 3643,2358 3643,2050 3647.8,2045.2 3647.8,1847.8 PL.10 ; 2783.34,2896.66 cw(c2816.67,2930) 2769.53,2930 ccw(c2816.67,2930) 2783.34,2896.66 ; 2783.34,2896.66 ccw(c2750,2863.33) 2750,2910.47 cw(c2750,2863.33) 2783.34,2896.66 ; 3633.34,1833.34 cw(c3600,1866.67) 3600,1819.53 ccw(c3600,1866.67) 3633.34,1833.34 ; 3633.34,1833.34 ccw(c3666.67,1800) 3619.53,1800 cw(c3666.67,1800) 3633.34,1833.34
NetPPI2_1: PPI2.1 U1.1 U2.1 | length 1876.4
  Top Layer w20: v1(2416,2822) 2550,2688 U2.1 2550,2558 2650,2458 U1.1 ; 2441.61,2796.39 cw(c2467.21,2822) 2431,2822 ccw(c2467.21,2822) 2441.61,2796.39 ; 2441.61,2796.39 ccw(c2416,2770.79) 2416,2807 cw(c2416,2770.79) 2441.61,2796.39 ; 2550,2582.86 cw(c2597.14,2582.86) 2563.81,2616.19 ccw(c2597.14,2582.86) 2550,2582.86 ; 2550,2582.86 ccw(c2502.86,2582.86) 2536.19,2616.19 cw(c2502.86,2582.86) 2550,2582.86 ; 2550,2677.14 cw(c2502.86,2677.14) 2536.19,2643.81 ccw(c2502.86,2677.14) 2550,2677.14 ; 2550,2677.14 ccw(c2597.14,2677.14) 2563.81,2643.81 cw(c2597.14,2677.14) 2550,2677.14 ; 2650,2277.14 cw(c2602.86,2277.14) 2636.19,2243.81 ccw(c2602.86,2277.14) 2650,2277.14 ; 2650,2277.14 ccw(c2697.14,2277.14) 2663.81,2243.81 cw(c2697.14,2277.14) 2650,2277.14
  Bottom Layer w20: PPI2.1 2242,3058 2242,3034.84 2416,2860.84 v1(2416,2822) ; 2233.34,3066.66 cw(c2266.67,3100) 2219.53,3100 ccw(c2266.67,3100) 2233.34,3066.66 ; 2233.34,3066.66 ccw(c2200,3033.33) 2200,3080.47 cw(c2200,3033.33) 2233.34,3066.66 ; 2416,2858.21 cw(c2379.79,2858.21) 2405.39,2832.61 ccw(c2379.79,2858.21) 2416,2858.21 ; 2416,2858.21 ccw(c2452.21,2858.21) 2426.61,2832.61 cw(c2452.21,2858.21) 2416,2858.21
NetPPI2_2: PPI2.2 U1.2 U2.2 | length 2117.1
  Top Layer w20: U1.2 2750,2430 2800,2480 2800,2555 2825,2580 2875,2580 2900,2605 2900,2680 v1(2883,2697) ; 2750,2277.14 cw(c2702.86,2277.14) 2736.19,2243.81 ccw(c2702.86,2277.14) 2750,2277.14 ; 2750,2277.14 ccw(c2797.14,2277.14) 2763.81,2243.81 cw(c2797.14,2277.14) 2750,2277.14
  Bottom Layer w20: PPI2.2 2371,2829 2371,2802 2424.75,2748.25 2503.75,2748.25 2542,2710 2755.53,2710 ; U2.2 2679.96,2630 2729.96,2580 2775,2580 2800,2605 2800,2665.53 2755.53,2710 ; v1(2883,2697) 2870,2710 2755.53,2710 ; 2233.34,2966.66 cw(c2266.67,3000) 2219.53,3000 ccw(c2266.67,3000) 2233.34,2966.66 ; 2233.34,2966.66 ccw(c2200,2933.33) 2200,2980.47 cw(c2200,2933.33) 2233.34,2966.66 ; 2815.4,2710 cw(c2815.4,2629.4) 2872.39,2686.39 ccw(c2815.4,2629.4) 2815.4,2710
NetPPI2_3: PPI2.3 U1.3 U2.3 | length 2109
  Top Layer w20: U2.3 2862,2742 2928,2742 3000,2670 3000,2605 2975,2580 2929.96,2580 2900,2550.04 2900,2471 2850,2421 U1.3 ; 2783.34,2663.34 cw(c2750,2696.67) 2750,2649.53 ccw(c2750,2696.67) 2783.34,2663.34 ; 2783.34,2663.34 ccw(c2816.67,2630) 2769.53,2630 cw(c2816.67,2630) 2783.34,2663.34 ; 2850,2277.14 cw(c2802.86,2277.14) 2836.19,2243.81 ccw(c2802.86,2277.14) 2850,2277.14 ; 2850,2277.14 ccw(c2897.14,2277.14) 2863.81,2243.81 cw(c2897.14,2277.14) 2850,2277.14
  Bottom Layer w20: PPI2.3 2381.75,2718.25 2487.82,2718.25 2526.07,2680 2700,2680 U2.3 ; 2233.34,2866.66 cw(c2266.67,2900) 2219.53,2900 ccw(c2266.67,2900) 2233.34,2866.66 ; 2233.34,2866.66 ccw(c2200,2833.33) 2200,2880.47 cw(c2200,2833.33) 2233.34,2866.66 ; 2716.66,2663.34 cw(c2683.33,2630) 2730.47,2630 ccw(c2683.33,2630) 2716.66,2663.34 ; 2716.66,2663.34 ccw(c2750,2696.67) 2750,2649.53 cw(c2750,2696.67) 2716.66,2663.34
NetPPI2_4: PPI2.4 U1.6 | length 3553.9
  Top Layer w20: PPI2.4 2265,2735 v1(2265,2610) ; v1(3150,1918) U1.6 ; 2233.34,2766.66 cw(c2266.67,2800) 2219.53,2800 ccw(c2266.67,2800) 2233.34,2766.66 ; 2233.34,2766.66 ccw(c2200,2733.33) 2200,2780.47 cw(c2200,2733.33) 2233.34,2766.66 ; 2265,2646.21 cw(c2228.79,2646.21) 2254.39,2620.61 ccw(c2228.79,2646.21) 2265,2646.21 ; 2265,2646.21 ccw(c2301.21,2646.21) 2275.61,2620.61 cw(c2301.21,2646.21) 2265,2646.21 ; 3150,1954.21 cw(c3113.79,1954.21) 3139.39,1928.61 ccw(c3113.79,1954.21) 3150,1954.21 ; 3150,1954.21 ccw(c3186.21,1954.21) 3160.61,1928.61 cw(c3186.21,1954.21) 3150,1954.21 ; 3150,2182.86 cw(c3197.14,2182.86) 3163.81,2216.19 ccw(c3197.14,2182.86) 3150,2182.86 ; 3150,2182.86 ccw(c3102.86,2182.86) 3136.19,2216.19 cw(c3102.86,2182.86) 3150,2182.86
  Bottom Layer w20: v1(2265,2610) 2295,2580 2295,2462 2283,2450 2175,2450 2150,2425 2150,2375 2125,2350 2075,2350 2050,2325 2050,1836 2139,1747 3125,1747 3150,1772 v1(3150,1918) ; 2290.61,2584.39 cw(c2316.21,2610) 2280,2610 ccw(c2316.21,2610) 2290.61,2584.39 ; 2290.61,2584.39 ccw(c2265,2558.79) 2265,2595 cw(c2265,2558.79) 2290.61,2584.39 ; 3150,1881.79 cw(c3186.21,1881.79) 3160.61,1907.39 ccw(c3186.21,1881.79) 3150,1881.79 ; 3150,1881.79 ccw(c3113.79,1881.79) 3139.39,1907.39 cw(c3113.79,1881.79) 3150,1881.79
NetPPI2_5: PPI2.5 U2.6 | length 1965.4
  Bottom Layer w20: PPI2.5 2261.43,2700 2381.43,2580 2675,2580 2700,2555 2700,2505 2725,2480 3275,2480 3300,2505 3300,2667.5 3287.5,2680 3100,2680 U2.6 ; 2247.14,2700 cw(c2247.14,2747.14) 2213.81,2713.81 ccw(c2247.14,2747.14) 2247.14,2700 ; 2247.14,2700 ccw(c2247.14,2652.86) 2213.81,2686.19 cw(c2247.14,2652.86) 2247.14,2700 ; 3083.34,2663.34 cw(c3050,2696.67) 3050,2649.53 ccw(c3050,2696.67) 3083.34,2663.34 ; 3083.34,2663.34 ccw(c3116.67,2630) 3069.53,2630 cw(c3116.67,2630) 3083.34,2663.34
NetPPI2_7: PPI2.7 RVCC.2 | length 562.5
  Top Layer w20: PPI2.7 2335,2500 2340,2505 2340,2596 2358,2596 2400,2638 RVCC.2 ; 2247.14,2500 cw(c2247.14,2547.14) 2213.81,2513.81 ccw(c2247.14,2547.14) 2247.14,2500 ; 2247.14,2500 ccw(c2247.14,2452.86) 2213.81,2486.19 cw(c2247.14,2452.86) 2247.14,2500 ; 2368.53,2606.53 ccw(c2342.71,2632.35) 2376.29,2646.68 cw(c2342.71,2632.35) 2368.53,2606.53
VCC: BT01.2 BT02.2 BT03.2 BT04.2 PL.11 PPI2.9 PUSB.1 U1.16 U2.16 | length 5846.5
  Top Layer w20: PUSB.1 2150,2050 2150,2250 PPI2.9 ; U2.16 2700,2780 2700,2580 U1.16 ; PL.11 BT01.2 BT02.2 BT03.2 ; 2133.34,2033.34 cw(c2100,2066.67) 2100,2019.53 ccw(c2100,2066.67) 2133.34,2033.34 ; 2133.34,2033.34 ccw(c2166.67,2000) 2119.53,2000 cw(c2166.67,2000) 2133.34,2033.34 ; 2166.66,2266.66 cw(c2200,2233.33) 2200,2280.47 ccw(c2200,2233.33) 2166.66,2266.66 ; 2166.66,2266.66 ccw(c2133.33,2300) 2180.47,2300 cw(c2133.33,2300) 2166.66,2266.66 ; 2583.34,2896.66 cw(c2616.67,2930) 2569.53,2930 ccw(c2616.67,2930) 2583.34,2896.66 ; 2583.34,2896.66 ccw(c2550,2863.33) 2550,2910.47 cw(c2550,2863.33) 2583.34,2896.66 ; 2683.34,2563.34 cw(c2650,2596.67) 2650,2549.53 ccw(c2650,2596.67) 2683.34,2563.34 ; 2683.34,2563.34 ccw(c2716.67,2530) 2669.53,2530 cw(c2716.67,2530) 2683.34,2563.34 ; 3700,1847.14 cw(c3652.86,1847.14) 3686.19,1813.81 ccw(c3652.86,1847.14) 3700,1847.14 ; 3700,1847.14 ccw(c3747.14,1847.14) 3713.81,1813.81 cw(c3747.14,1847.14) 3700,1847.14 ; 3700,1852.86 cw(c3747.14,1852.86) 3713.81,1886.19 ccw(c3747.14,1852.86) 3700,1852.86 ; 3700,1852.86 ccw(c3652.86,1852.86) 3686.19,1886.19 cw(c3652.86,1852.86) 3700,1852.86 ; 3700,1947.14 cw(c3652.86,1947.14) 3686.19,1913.81 ccw(c3652.86,1947.14) 3700,1947.14 ; 3700,1947.14 ccw(c3747.14,1947.14) 3713.81,1913.81 cw(c3747.14,1947.14) 3700,1947.14 ; 3700,1952.86 cw(c3747.14,1952.86) 3713.81,1986.19 ccw(c3747.14,1952.86) 3700,1952.86 ; 3700,1952.86 ccw(c3652.86,1952.86) 3686.19,1986.19 cw(c3652.86,1952.86) 3700,1952.86 ; 3700,2047.14 cw(c3652.86,2047.14) 3686.19,2013.81 ccw(c3652.86,2047.14) 3700,2047.14 ; 3700,2047.14 ccw(c3747.14,2047.14) 3713.81,2013.81 cw(c3747.14,2047.14) 3700,2047.14 ; 3700,2052.86 cw(c3747.14,2052.86) 3713.81,2086.19 ccw(c3747.14,2052.86) 3700,2052.86 ; 3700,2052.86 ccw(c3652.86,2052.86) 3686.19,2086.19 cw(c3652.86,2052.86) 3700,2052.86
  Bottom Layer w20: PUSB.1 2180,1920 2850,1920 ; PPI2.9 2242.2,2342.2 2242.2,2365.36 2356.81,2479.97 2356.81,2506.57 2380.24,2530 U1.16 ; BT04.2 2900,1970 2850,1920 ; BT03.2 3642.2,2157.8 3334.64,2157.8 3154.14,1977.3 3124.14,1977.3 3066.84,1920 2850,1920 ; 2133.34,1966.66 cw(c2166.67,2000) 2119.53,2000 ccw(c2166.67,2000) 2133.34,1966.66 ; 2133.34,1966.66 ccw(c2100,1933.33) 2100,1980.47 cw(c2100,1933.33) 2133.34,1966.66 ; 2233.34,2333.34 cw(c2200,2366.67) 2200,2319.53 ccw(c2200,2366.67) 2233.34,2333.34 ; 2233.34,2333.34 ccw(c2266.67,2300) 2219.53,2300 cw(c2266.67,2300) 2233.34,2333.34 ; 2602.86,2530 cw(c2602.86,2482.86) 2636.19,2516.19 ccw(c2602.86,2482.86) 2602.86,2530 ; 2602.86,2530 ccw(c2602.86,2577.14) 2636.19,2543.81 cw(c2602.86,2577.14) 2602.86,2530 ; 3666.66,2133.34 cw(c3633.33,2100) 3680.47,2100 ccw(c3633.33,2100) 3666.66,2133.34 ; 3666.66,2133.34 ccw(c3700,2166.67) 3700,2119.53 cw(c3700,2166.67) 3666.66,2133.34 ; 2865,1935 ccw(c2821.02,1978.98) 2881.13,1994.98 cw(c2821.02,1978.98) 2865,1935 ; 2889.55,1959.55 ccw(c2859.79,1989.3) 2900.46,2000.12 cw(c2859.79,1989.3) 2889.55,1959.55
pads on no net: PPI2.6 PPI2.8 PUSB.2 PUSB.3 PUSB.4 U2.7 U2.9 U2.10 U2.11 U2.12 U2.13

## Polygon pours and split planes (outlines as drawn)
GND on Top Layer "Top Layer-No Net" (solid): 3890,1710 2010,1710 2000,1700 2000,3600 3890,3600 3890,1710
GND on Bottom Layer "Top Layer-No Net" (solid): 2000,1700 2000,3600 3890,3600 3890,1710 3880,1700 2000,1700

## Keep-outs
Keep-Out Layer:
  lines w10: 2000,1700 2000,3600 3890,3600 3890,1700 2000,1700

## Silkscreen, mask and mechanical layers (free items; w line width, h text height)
Mechanical 1:
  lines w10: 2000,1700 2000,3600 3890,3600 3890,1710 2010,1710 2000,1700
